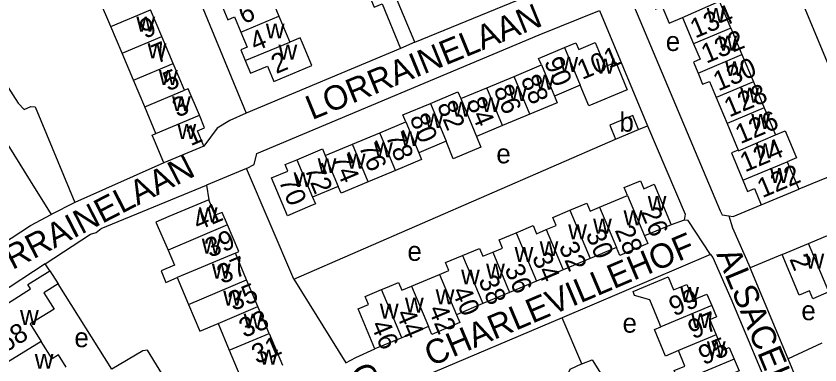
# Model space of a CAD drawing. Extents: x 157768 to 159790, y 387230 to 389604.
# Drawn here: x 158696.4 to 158862.1, y 388397.7 to 388469.5 of the extents above; entities that cross this region are included whole.
import ezdxf

# ---------------------------------------------------------------- set-up
doc = ezdxf.new("R2010")
doc.units = 0
for name, color, linetype in [('BLT_Basislijn', 7, 'Continuous'), ('BLT_Bebouwing', 7, 'Continuous'), ('BLT_Centroide', 7, 'Continuous'), ('BLT_Huisnummer', 7, 'Continuous'), ('BLT_Huisnummer_ tussenligend', 7, 'Continuous'), ('BLT_Huisnummer_reeks', 7, 'Continuous'), ('BLT_Onderverdeling_panden', 7, 'Continuous'), ('BLT_Straatnaam', 7, 'Continuous')]:
    doc.layers.add(name, color=color, linetype=linetype)

msp = doc.modelspace()

# ---------------------------------------------------------------- linework, layer by layer
at = {"layer": 'BLT_Basislijn'}
for p, q in [((158668.08, 388485.63), (158699.32, 388435.61)), ((158858.27, 388472.75), (158871.67, 388440.58)), ((158824.7, 388446.2), (158826.54, 388446.97)), ((158753.68, 388415.36), (158819.96, 388444.23)), ((158726.87, 388439.31), (158708.5, 388431.14)), ((158743.87, 388438.13), (158735.62, 388434.76)), ((158753.68, 388415.36), (158743.87, 388438.13)), ((158699.32, 388435.61), (158703.65, 388428.68)), ((158735.62, 388434.76), (158736.13, 388431.71)), ((158708.5, 388431.14), (158703.65, 388428.68)), ((158834.13, 388427.52), (158831.41, 388426.59)), ((158839.56, 388420.42), (158808.94, 388407.39)), ((158854.29, 388420.43), (158847.74, 388417.73)), ((158702.43, 388418.55), (158686.58, 388408.19)), ((158703.36, 388417.09), (158702.43, 388418.55)), ((158855.53, 388398.97), (158847.74, 388417.73)), ((158716.17, 388396.8), (158705.05, 388414.38)), ((158813.02, 388397.93), (158808.94, 388407.39)), ((158862.46, 388402.16), (158855.53, 388398.97)), ((158867.4, 388370.67), (158855.53, 388398.97))]:
    msp.add_line(p, q, dxfattribs=at)
for points in [[(158778.58, 388464.15), (158808.82, 388476.57), (158799.98, 388500), (158781.37, 388543.21)], [(158778.58, 388464.15), (158774.78, 388473.27), (158776.21, 388473.86), (158755.39, 388523.57), (158753.12, 388522.63), (158749.99, 388530.03)], [(158748.73, 388529.24), (158746.01, 388527.42), (158718.77, 388510.31), (158720.12, 388506.59), (158723, 388500), (158743.81, 388449.55)], [(158748.73, 388529.24), (158751.69, 388522.02), (158749.43, 388521.09), (158770.23, 388471.39), (158771.83, 388472.05), (158775.66, 388462.85)], [(158821.11, 388491.65), (158812.62, 388488.1), (158812.14, 388487.84), (158812.15, 388487.34), (158815.59, 388479.7), (158820.7, 388477.74), (158821.99, 388475.76), (158841.52, 388429.43), (158841.92, 388428.6), (158843.29, 388428.39)], [(158666.55, 388488.08), (158671.82, 388490.71), (158696.85, 388451.62), (158698.07, 388450.32), (158699.45, 388450.96), (158700.33, 388450.83), (158708.5, 388431.14)], [(158743.87, 388438.13), (158745.5, 388438.98), (158746.04, 388441.22), (158804.21, 388465.72), (158816.65, 388470.68), (158826.54, 388446.97)], [(158778.58, 388464.15), (158775.66, 388462.85)], [(158775.66, 388462.85), (158743.81, 388449.55)], [(158743.81, 388449.55), (158740.45, 388448.07), (158737.83, 388446.48), (158735.13, 388442.79)], [(158826.54, 388446.97), (158834.3, 388428.75), (158834.13, 388427.52)], [(158871.67, 388440.58), (158867.65, 388437.98), (158857.71, 388433.89)], [(158702.43, 388418.55), (158711.74, 388424.64), (158712.94, 388425.01), (158713.96, 388425.77), (158735.62, 388434.76)], [(158843.29, 388428.39), (158844.19, 388428.29), (158850, 388430.65)], [(158679.39, 388413.35), (158699.36, 388426.4), (158703.65, 388428.68)], [(158843.29, 388428.39), (158844.09, 388425.94), (158847.74, 388417.73)], [(158839.56, 388420.42), (158834.95, 388427.45), (158834.13, 388427.52)], [(158839.56, 388420.42), (158840.04, 388419.86), (158843.73, 388411.41), (158862.28, 388367.15), (158869.98, 388349.5), (158869.66, 388346.59), (158868.7, 388345.1), (158842.64, 388334.43)], [(158753.68, 388415.36), (158764.34, 388398.1), (158766.42, 388399.22), (158770.35, 388400.99)], [(158808.94, 388407.39), (158780.46, 388395.33), (158776.82, 388393.62), (158776.79, 388393.22), (158807.64, 388319.88)], [(158749.97, 388353.67), (158732.88, 388381.58), (158734.22, 388382.93), (158734.22, 388383.32), (158723.46, 388400.72), (158722.5, 388400.61), (158716.17, 388396.8)], [(158813.02, 388397.93), (158815.11, 388398.74), (158816.98, 388395.83), (158842.64, 388334.43)], [(158813.02, 388397.93), (158810.55, 388396.78), (158810, 388395.49), (158836.9, 388332.08)]]:
    msp.add_lwpolyline(points, dxfattribs=at)
at = {"layer": 'BLT_Bebouwing'}
for p, q in [((158748.26, 388475.09), (158750.58, 388469.54)), ((158726.45, 388465.32), (158724.13, 388470.84)), ((158750.58, 388469.54), (158752.81, 388464.2)), ((158833.75, 388469.28), (158836.04, 388463.82)), ((158718.27, 388461.88), (158715.95, 388467.39)), ((158843.74, 388467.05), (158846.02, 388461.61)), ((158728.77, 388459.81), (158726.45, 388465.32)), ((158720.59, 388456.37), (158718.27, 388461.88)), ((158846.02, 388461.61), (158848.38, 388455.99)), ((158731.09, 388454.3), (158728.77, 388459.81)), ((158799.04, 388457.14), (158804.67, 388459.49)), ((158793.42, 388454.79), (158799.04, 388457.14)), ((158722.91, 388450.85), (158720.59, 388456.37)), ((158788.05, 388452.55), (158793.42, 388454.79)), ((158812.67, 388455.29), (158807.35, 388453.06)), ((158848.38, 388455.99), (158850.62, 388450.64)), ((158840.71, 388452.78), (158842.96, 388447.43)), ((158725.23, 388445.34), (158722.91, 388450.85)), ((158850.62, 388450.64), (158852.95, 388445.1)), ((158802.3, 388449.34), (158796.68, 388446.99)), ((158771.36, 388445.53), (158776.74, 388447.78)), ((158842.96, 388447.43), (158845.26, 388441.96)), ((158765.75, 388443.18), (158771.36, 388445.53)), ((158819.96, 388444.23), (158824.7, 388446.2)), ((158760.14, 388440.84), (158765.75, 388443.18)), ((158785.06, 388443.78), (158779.4, 388441.41)), ((158735.13, 388442.79), (158726.87, 388439.31)), ((158774.61, 388437.75), (158769, 388435.4)), ((158762.82, 388434.43), (158757.53, 388432.22)), ((158850, 388430.65), (158857.71, 388433.89)), ((158816.66, 388430.17), (158822.45, 388432.6)), ((158831.41, 388426.59), (158825.94, 388424.29)), ((158859.73, 388422.72), (158865.43, 388425.13)), ((158820.14, 388421.88), (158814.71, 388419.6)), ((158854.29, 388420.43), (158859.73, 388422.72)), ((158743.92, 388415.23), (158741.6, 388420.75)), ((158814.71, 388419.6), (158809.17, 388417.28)), ((158703.37, 388417.09), (158705.05, 388414.39)), ((158809.17, 388417.28), (158803.65, 388414.96)), ((158746.25, 388409.72), (158743.92, 388415.23)), ((158777.92, 388413.95), (158783.67, 388416.36)), ((158803.65, 388414.96), (158798.13, 388412.64)), ((158798.13, 388412.64), (158792.59, 388410.32)), ((158792.59, 388410.32), (158787.16, 388408.04)), ((158748.58, 388404.2), (158746.25, 388409.72)), ((158738.03, 388406.25), (158740.35, 388400.73)), ((158781.41, 388405.63), (158775.88, 388403.31)), ((158748.58, 388404.2), (158751.35, 388397.63)), ((158775.88, 388403.31), (158770.35, 388400.99))]:
    msp.add_line(p, q, dxfattribs=at)
for points in [[(158715.95, 388467.39), (158713.63, 388472.9), (158715.5, 388473.69)], [(158827.15, 388473.43), (158828.18, 388470.97), (158829.55, 388471.54), (158830.99, 388468.12), (158833.75, 388469.28)], [(158843.74, 388467.05), (158843.24, 388468.23), (158841.39, 388472.64)], [(158739.05, 388471.24), (158740.06, 388468.81), (158741.44, 388469.38), (158742.74, 388466.27)], [(158742.74, 388466.27), (158744.04, 388463.15), (158742.7, 388462.59), (158743.63, 388460.37)], [(158743.63, 388460.37), (158744.71, 388457.79), (158748.2, 388459.24), (158749.53, 388456.08), (158757.35, 388459.34), (158755.43, 388463.96), (158754.95, 388465.09), (158752.81, 388464.2)], [(158804.67, 388459.49), (158804.1, 388460.84), (158809.43, 388463.06)], [(158809.43, 388463.06), (158811.79, 388464.05), (158812.37, 388462.67), (158815.77, 388464.09), (158817.82, 388459.17), (158820, 388460.08), (158822.38, 388454.38), (158814.44, 388451.06), (158812.67, 388455.29)], [(158836.04, 388463.82), (158837.37, 388460.66), (158836, 388460.08), (158836.96, 388457.8)], [(158836.96, 388457.8), (158837.91, 388455.53), (158839.32, 388456.11), (158840.71, 388452.78)], [(158734.2, 388449.11), (158731.89, 388454.59), (158731.09, 388454.3)], [(158781.81, 388451.57), (158787.47, 388453.93), (158788.05, 388452.55)], [(158776.74, 388447.78), (158776.15, 388449.2), (158781.81, 388451.57)], [(158807.35, 388453.06), (158807.92, 388451.69), (158802.3, 388449.34)], [(158735.13, 388442.79), (158733.8, 388445.93), (158735.27, 388446.55), (158734.2, 388449.11)], [(158824.7, 388446.2), (158823.51, 388449.04), (158818.78, 388447.06), (158819.96, 388444.23)], [(158796.68, 388446.99), (158791.3, 388444.75)], [(158726.87, 388439.31), (158724.93, 388443.92), (158724.46, 388445.02), (158725.23, 388445.34)], [(158852.95, 388445.1), (158854.91, 388445.95), (158857.23, 388440.35), (158855.33, 388439.56)], [(158791.3, 388444.75), (158792.21, 388442.54), (158786.52, 388440.15), (158785.06, 388443.78)], [(158754.29, 388439.97), (158759.58, 388442.18), (158760.14, 388440.84)], [(158845.26, 388441.96), (158843.84, 388441.36), (158846.18, 388435.78)], [(158757.53, 388432.22), (158758.1, 388430.85), (158756.95, 388430.37), (158752.33, 388428.44), (158749.08, 388436.22), (158752.42, 388437.61), (158751.86, 388438.96), (158754.29, 388439.97)], [(158779.4, 388441.41), (158779.99, 388440), (158774.61, 388437.75)], [(158855.33, 388439.56), (158857.71, 388433.89)], [(158769, 388435.4), (158763.39, 388433.06), (158762.82, 388434.43)], [(158822.45, 388432.6), (158821.77, 388434.22), (158825.09, 388435.62), (158825.77, 388433.99), (158827.92, 388434.9), (158831.41, 388426.59)], [(158846.18, 388435.78), (158847.15, 388433.45), (158848.57, 388434.04), (158850, 388430.65)], [(158736.13, 388431.71), (158727.9, 388428.24), (158725.22, 388427.11), (158727.74, 388421.37)], [(158740, 388426.54), (158738.9, 388429.13), (158737.47, 388428.52), (158736.13, 388431.71)], [(158810.53, 388429.56), (158814.05, 388431.04), (158814.75, 388429.37), (158816.66, 388430.17)], [(158805.68, 388425.57), (158807.71, 388426.42), (158807.01, 388428.09), (158810.53, 388429.56)], [(158741.6, 388420.75), (158742.31, 388421.05), (158740, 388426.54)], [(158799.47, 388424.93), (158802.96, 388426.39), (158803.66, 388424.72), (158805.68, 388425.57)], [(158794.65, 388420.93), (158796.68, 388421.78), (158795.98, 388423.46), (158799.47, 388424.93)], [(158825.94, 388424.29), (158826.61, 388422.7), (158820.82, 388420.27), (158820.14, 388421.88)], [(158788.43, 388420.24), (158791.93, 388421.71), (158792.62, 388420.08), (158794.65, 388420.93)], [(158727.74, 388421.37), (158729.07, 388418.23)], [(158783.67, 388416.36), (158785.59, 388417.17), (158784.92, 388418.77), (158788.43, 388420.24)], [(158863.93, 388412.74), (158860.61, 388411.34), (158859.92, 388412.98), (158857.81, 388412.09), (158854.29, 388420.43)], [(158689.39, 388403.66), (158693.62, 388406.29), (158692.06, 388408.79), (158699.4, 388413.36), (158698.83, 388414.26), (158703.36, 388417.09)], [(158729.07, 388418.23), (158726.3, 388417.06)], [(158726.3, 388417.06), (158727.29, 388414.71)], [(158727.29, 388414.71), (158729.6, 388415.68)], [(158729.6, 388415.68), (158731.92, 388410.17)], [(158829.29, 388405.57), (158828.92, 388406.47), (158827, 388411.09), (158823.9, 388411.97), (158823.56, 388412.8), (158830.81, 388415.82), (158831.93, 388413.14), (158834.67, 388414.28), (158835.98, 388411.13), (158838.79, 388412.3), (158839.78, 388409.94)], [(158705.05, 388414.38), (158702.15, 388412.57), (158704.25, 388409.21), (158699.33, 388406.14), (158701.57, 388402.55)], [(158771.72, 388413.22), (158772.93, 388413.73), (158775.25, 388414.7), (158775.92, 388413.11), (158777.92, 388413.95)], [(158770.35, 388400.99), (158766.88, 388409.24), (158769.01, 388410.14), (158768.32, 388411.79), (158771.72, 388413.22)], [(158731.92, 388410.17), (158734.25, 388404.66), (158738.03, 388406.25)], [(158839.78, 388409.94), (158840.76, 388407.58), (158839.39, 388407.01), (158840.69, 388403.87)], [(158787.16, 388408.04), (158787.85, 388406.41), (158782.1, 388403.99), (158781.41, 388405.63)], [(158832.92, 388400.64), (158830.26, 388399.53), (158827.97, 388405.02), (158829.29, 388405.57)], [(158840.69, 388403.87), (158841.99, 388400.74), (158843.41, 388401.32), (158844.42, 388398.89)], [(158706.73, 388397.27), (158705.15, 388399.8), (158703.81, 388398.96), (158701.57, 388402.55)], [(158740.35, 388400.73), (158742.55, 388395.52)], [(158835.23, 388395.07), (158833.04, 388394.17), (158832.05, 388396.55), (158834.24, 388397.46), (158832.92, 388400.64)], [(158844.42, 388398.89), (158845.43, 388396.47), (158844.13, 388395.93), (158845.44, 388392.78)]]:
    msp.add_lwpolyline(points, dxfattribs=at)
at = {"layer": 'BLT_Onderverdeling_panden'}
for p, q in [((158715.95, 388467.39), (158724.13, 388470.84)), ((158742.74, 388466.27), (158750.58, 388469.54)), ((158843.74, 388467.05), (158836.04, 388463.82)), ((158718.27, 388461.88), (158726.45, 388465.32)), ((158743.63, 388460.37), (158752.81, 388464.2)), ((158809.43, 388463.06), (158812.67, 388455.29)), ((158836.96, 388457.8), (158846.02, 388461.61)), ((158720.59, 388456.37), (158728.77, 388459.81)), ((158804.67, 388459.49), (158807.35, 388453.06)), ((158802.3, 388449.34), (158799.04, 388457.14)), ((158796.68, 388446.99), (158793.42, 388454.79)), ((158848.38, 388455.99), (158840.71, 388452.78)), ((158722.91, 388450.85), (158731.09, 388454.3)), ((158781.81, 388451.57), (158785.06, 388443.78)), ((158788.05, 388452.55), (158791.3, 388444.75)), ((158850.62, 388450.64), (158842.96, 388447.43)), ((158725.23, 388445.34), (158734.2, 388449.11)), ((158776.74, 388447.78), (158779.4, 388441.41)), ((158774.61, 388437.75), (158771.36, 388445.53)), ((158769, 388435.4), (158765.75, 388443.18)), ((158754.29, 388439.97), (158757.53, 388432.22)), ((158760.14, 388440.84), (158762.82, 388434.43)), ((158846.18, 388435.78), (158855.33, 388439.56)), ((158822.45, 388432.6), (158825.94, 388424.29)), ((158816.66, 388430.17), (158820.14, 388421.88)), ((158810.53, 388429.56), (158814.71, 388419.6)), ((158740, 388426.54), (158727.74, 388421.37)), ((158805.68, 388425.57), (158809.17, 388417.28)), ((158799.47, 388424.93), (158803.65, 388414.96)), ((158863.93, 388412.74), (158859.73, 388422.72)), ((158741.6, 388420.75), (158729.6, 388415.68)), ((158788.43, 388420.24), (158792.59, 388410.32)), ((158794.65, 388420.93), (158798.13, 388412.64)), ((158731.92, 388410.17), (158743.92, 388415.23)), ((158783.67, 388416.36), (158787.16, 388408.04)), ((158777.92, 388413.95), (158781.41, 388405.63)), ((158775.88, 388403.31), (158771.72, 388413.22)), ((158738.03, 388406.25), (158746.25, 388409.72)), ((158839.78, 388409.94), (158829.29, 388405.57)), ((158740.35, 388400.73), (158748.58, 388404.2)), ((158840.69, 388403.87), (158832.92, 388400.64)), ((158701.57, 388402.55), (158693.88, 388397.76)), ((158844.42, 388398.89), (158835.23, 388395.07))]:
    msp.add_line(p, q, dxfattribs=at)
for points in [[(158833.75, 388469.28), (158841.39, 388472.64)], [(158845.26, 388441.96), (158845.31, 388441.83), (158852.95, 388445.1)]]:
    msp.add_lwpolyline(points, dxfattribs=at)

# ---------------------------------------------------------------- texts
at = {"layer": 'BLT_Centroide'}
for s, p in [('w', (158838.74, 388468.16)), ('w', (158721.2, 388466.34)), ('w', (158747.88, 388464.94)), ('e', (158830.31, 388462.36)), ('w', (158841.15, 388462.44)), ('w', (158723.52, 388460.84)), ('w', (158750.49, 388460.59)), ('w', (158808.39, 388458.06)), ('w', (158815.91, 388457.7)), ('w', (158842.55, 388457.19)), ('w', (158725.84, 388455.34)), ('w', (158803.48, 388454.42)), ('w', (158797.86, 388452.08)), ('w', (158845.66, 388451.72)), ('w', (158728.55, 388449.97)), ('w', (158786.27, 388448.86)), ('w', (158792.36, 388449.77)), ('b', (158820.76, 388445.74)), ('w', (158780.61, 388446.48)), ('w', (158847.94, 388446.31)), ('w', (158729.66, 388444.22)), ('w', (158775.67, 388442.77)), ('w', (158770.19, 388440.47)), ('w', (158848.86, 388440.25)), ('e', (158795.39, 388439.22)), ('w', (158758.56, 388437.2)), ('w', (158764.56, 388438.12)), ('w', (158851.8, 388435.19)), ('w', (158753.59, 388434.33)), ('w', (158826.59, 388429.45)), ('w', (158734.07, 388427.09)), ('w', (158821.62, 388426.44)), ('w', (158810.2, 388423.58)), ('w', (158815.33, 388424.75)), ('w', (158734.68, 388420.62)), ('e', (158777.06, 388419.14)), ('w', (158799.16, 388418.92)), ('w', (158804.31, 388420.12)), ('w', (158859.11, 388417.56)), ('w', (158736.76, 388415.47)), ('w', (158793.28, 388415.47)), ('w', (158788.12, 388414.28)), ('w', (158833.3, 388410.69)), ('w', (158739.09, 388409.94)), ('w', (158782.89, 388410.17)), ('w', (158771.38, 388407.23)), ('w', (158776.56, 388408.48)), ('w', (158697.22, 388405.92)), ('e', (158858.25, 388406.91)), ('w', (158743.3, 388405.22)), ('e', (158821.4, 388404.34)), ('w', (158835.54, 388405.28)), ('e', (158708.42, 388401.35)), ('w', (158838.79, 388399.47)), ('w', (158746.53, 388397.78)), ('w', (158700.25, 388396.91))]:
    msp.add_text(s, height=4, dxfattribs=at).set_placement(p)
at = {"layer": 'BLT_Huisnummer'}
for s, rotation, p in [('6', 22.6495, (158743.28, 388467.84)), ('134', 22.7679, (158836.38, 388464.92)), ('2', 22.6495, (158750.02, 388457.59)), ('101', 22.5943, (158813.08, 388456.39)), ('90', 292.6692, (158805.17, 388460.19)), ('130', 22.7679, (158841.13, 388454.03)), ('5', 22.825, (158727.72, 388454)), ('86', 292.6659, (158794.76, 388454.49)), ('82', 292.6659, (158783.11, 388451.16)), ('126', 22.7679, (158845.69, 388443.15)), ('1', 22.825, (158732.39, 388442.74)), ('78', 292.6659, (158772.52, 388444.81)), ('74', 292.6659, (158761.33, 388440.31)), ('122', 22.7679, (158850.21, 388432.03)), ('70', 292.6659, (158750.47, 388435.61)), ('41', 22.872, (158733.9, 388425.33)), ('26', 292.7768, (158825.06, 388429.23)), ('30', 292.7768, (158813.74, 388424.66)), ('34', 292.7768, (158802.68, 388419.89)), ('2', 292.8718, (158855.74, 388419.53)), ('38', 292.7768, (158791.63, 388415.18)), ('35', 22.872, (158741.18, 388408.75)), ('99', 22.5943, (158832, 388407.66)), ('42', 292.7768, (158781.3, 388409.15)), ('46', 292.7768, (158769.45, 388405.98)), ('31', 22.872, (158745.99, 388397.84))]:
    msp.add_text(s, height=4, rotation=rotation, dxfattribs=at).set_placement(p)
at = {"layer": 'BLT_Huisnummer_ tussenligend'}
for s, rotation, p in [('9', 22.825, (158722.92, 388464.82)), ('4', 22.6495, (158745.66, 388462.2)), ('132', 22.7679, (158838.66, 388459.72)), ('7', 22.825, (158725.4, 388459.67)), ('88', 292.6659, (158800.35, 388456.54)), ('128', 22.7679, (158843.39, 388448.65)), ('3', 22.825, (158729.67, 388448.6)), ('84', 292.6659, (158789.16, 388451.93)), ('80', 292.6659, (158777.45, 388448.56)), ('76', 292.6659, (158766.98, 388442.7)), ('124', 22.7679, (158846.65, 388437.34)), ('72', 292.6659, (158755.8, 388438.08)), ('39', 22.872, (158736.39, 388419.72)), ('28', 292.7768, (158819.74, 388425.49)), ('32', 292.7768, (158808.2, 388422.12)), ('37', 22.872, (158738.86, 388414.3)), ('36', 292.7768, (158797.01, 388417.51)), ('40', 292.7768, (158786.18, 388412.9)), ('33', 22.872, (158743.41, 388403.22)), ('44', 292.7768, (158774.64, 388408.28)), ('97', 22.5943, (158835.92, 388402.93)), ('95', 22.5943, (158838.07, 388397.61))]:
    msp.add_text(s, height=4, rotation=rotation, dxfattribs=at).set_placement(p)
at = {"layer": 'BLT_Huisnummer_reeks'}
msp.add_text('68', height=4, rotation=32.0186, dxfattribs=at).set_placement((158694.19, 388400.12))
at = {"layer": 'BLT_Straatnaam'}
for s, height, rotation, p in [('LORRAINELAAN', 4.9999, 22.2595, (158757.4, 388448.1)), ('LORRAINELAAN', 5, 27.2595, (158687.73, 388413.13)), ('CHARLEVILLEHOF', 5, 22.9698, (158781.93, 388397.33)), ('ALSACELAAN', 5, 292.6307, (158840.67, 388420.51)), ('CHARLEVILLEHOF', 4.9999, 296.9698, (158764.93, 388396.54))]:
    msp.add_text(s, height=height, rotation=rotation, dxfattribs=at).set_placement(p)

doc.saveas('drawing.dxf')
